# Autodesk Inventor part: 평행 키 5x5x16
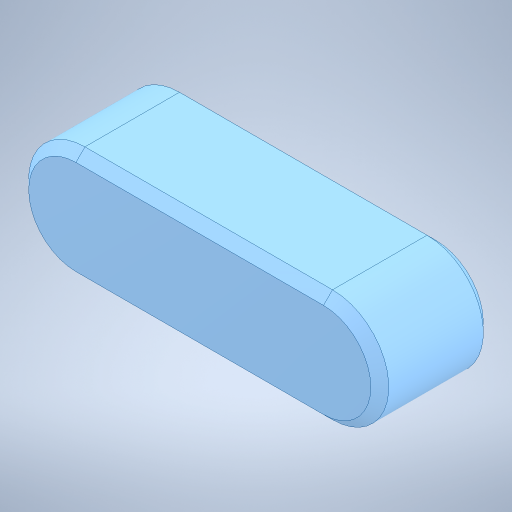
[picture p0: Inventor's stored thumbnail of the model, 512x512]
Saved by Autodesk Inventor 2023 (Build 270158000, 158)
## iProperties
Created: 2026-07
Part Number: 평행 키 5x5x16
Material: 강철, 연강
Description: 키 및 해당 키홈
Document SubType Name: Modeling
Designer: home
Density: 7.85 g/cm^3
Appearance: 기본값
Author: jhkim
Sending System: Autodesk Inventor 2027
Preprocessor: ST-DEVELOPER v20.1
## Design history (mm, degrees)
feature "Solid1"
node "솔리드1"
